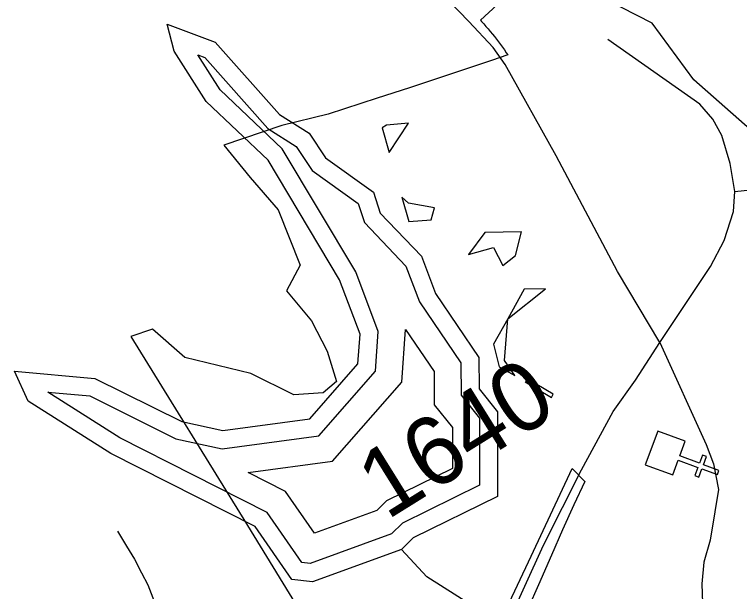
# Model space of a CAD drawing. Extents: x 2001466 to 31450019, y -30647475 to 847247.
# Drawn here: x 31437067 to 31439706, y -30623518 to -30621416 of the extents above; entities that cross this region are included whole.
import ezdxf

# ---------------------------------------------------------------- set-up
doc = ezdxf.new("R2010")
doc.units = 0
for name, color, linetype in [('Exist Boundary Political City Limit New Hole', 7, 'Continuous'), ('Exist Cultural Church CELL', 7, 'Continuous'), ('Exist Hydrographic Buffer Line', 7, 'Continuous'), ('Exist Hydrographic Creek Single Shore', 7, 'Continuous'), ('Exist Hydrographic Lake Shore', 7, 'Continuous'), ('Exist Road Non-System Type 51', 7, 'Continuous'), ('Exist Road Secondary Type 51 Attributed', 7, 'Continuous'), ('Exist Road Secondary Type 51 Number Label', 7, 'Continuous'), ('Map Preparation Boundary City Limit Buffer Line', 7, 'Continuous')]:
    doc.layers.add(name, color=color, linetype=linetype)

msp = doc.modelspace()

# ---------------------------------------------------------------- linework, layer by layer
at = {"layer": 'Exist Boundary Political City Limit New Hole'}
for points in [[(31438430.3, -30621919.4), (31438500.8, -30621812.3), (31438421, -30621819.8), (31438404.8, -30621829.8), (31438430.3, -30621919.4)], [(31438501.4, -30622104), (31438476.8, -30622082.1), (31438502.1, -30622170.6), (31438583, -30622164.5), (31438596, -30622120.6), (31438501.4, -30622104)], [(31438889.9, -30622293.8), (31438912, -30622208.7), (31438779, -30622211), (31438719.3, -30622291.1), (31438810.8, -30622265.3), (31438844.6, -30622330.2), (31438889.9, -30622293.8)], [(31438862.9, -30622525.3), (31438999.4, -30622415.7), (31438921.6, -30622416.9), (31438862.9, -30622525.3)], [(31438862.9, -30622525.3), (31438810.3, -30622617), (31438831, -30622699.5), (31438887.9, -30622731.8)], [(31438887.9, -30622731.8), (31438851, -30622676.8), (31438862.9, -30622525.3)], [(31438925.9, -30622754), (31439021.5, -30622811.4), (31439027.8, -30622799.3), (31438968.4, -30622764.3), (31438966.3, -30622763.8), (31438925.9, -30622754)]]:
    msp.add_lwpolyline(points, dxfattribs=at)
at = {"layer": 'Exist Cultural Church CELL'}
msp.add_lwpolyline([(31439408.4, -30622934.2), (31439363, -30623056.7), (31439462.8, -30623093.7), (31439483, -30623039.7), (31439554.4, -30623066.1), (31439543.3, -30623096.1), (31439558.2, -30623101.7), (31439569.4, -30623071.7), (31439625.7, -30623092.5), (31439631.3, -30623077.5), (31439574.9, -30623056.6), (31439586, -30623026.6), (31439571, -30623021.1), (31439559.9, -30623051.1), (31439488.5, -30623024.6), (31439508.2, -30622971.2), (31439408.4, -30622934.2)], dxfattribs=at)
at = {"layer": 'Exist Hydrographic Buffer Line'}
for points in [[(31437187.3, -30622792.6), (31437340.4, -30622806.1), (31437653.6, -30622961.6), (31437822.8, -30622998.4), (31438174.6, -30622950.7), (31438380.3, -30622716), (31438391, -30622571.4), (31438308.8, -30622354), (31438041.2, -30621906.3), (31437815.5, -30621691), (31437733.8, -30621563.3)], [(31437733.8, -30621563.3), (31437759, -30621572.8), (31437988.6, -30621831.7), (31438092.4, -30621896.9), (31438150.3, -30621985), (31438317.9, -30622104.6), (31438340.6, -30622174.2), (31438491.7, -30622332.6), (31438540.8, -30622462.9), (31438692, -30622685.8), (31438693, -30622803.4), (31438758.9, -30622886.6), (31438759.7, -30623131.3), (31438478.9, -30623269.1), (31438439.4, -30623308.4)], [(31437916.8, -30623085), (31438224.3, -30623043.3), (31438476.1, -30622756.1), (31438490.3, -30622563.8)], [(31438490.3, -30622563.8), (31438593.8, -30622716.4), (31438594.9, -30622838), (31438660.6, -30622921), (31438661.1, -30623070), (31438420.9, -30623187.9), (31438385.3, -30623223.3)], [(31438439.4, -30623308.4), (31438143.3, -30623416.2), (31438113.2, -30623413), (31437987, -30623231), (31437449.8, -30622958.2), (31437187.3, -30622792.6)], [(31438385.3, -30623223.3), (31438158.7, -30623305.9), (31438053.7, -30623154.5), (31437916.8, -30623085)]]:
    msp.add_lwpolyline(points, dxfattribs=at)
at = {"layer": 'Exist Hydrographic Creek Single Shore'}
for points in [[(31439888.4, -30621961.3), (31439539.5, -30621654.5), (31439388.3, -30621448), (31438996.5, -30621246.3), (31438888.4, -30621129.3), (31438779.3, -30620940), (31438746.5, -30620821.2), (31438753.5, -30620214.4), (31438794.3, -30620077.4)], [(31440512.4, -30625135.9), (31440412.4, -30625078), (31440328.5, -30624787.5), (31440294.5, -30624770.5), (31440277.4, -30624694.7), (31440194.4, -30624627.4), (31439927.4, -30624579.3), (31439877.4, -30624443.7), (31439760.5, -30624369.1), (31439693.5, -30624262.8), (31439260.4, -30624053.8), (31438998.6, -30623756.5), (31438963.5, -30623729.3), (31438939.7, -30623703.8), (31438905.2, -30623679.5), (31438856.5, -30623647.7), (31438567.5, -30623465.4), (31438475.4, -30623365.1)]]:
    msp.add_lwpolyline(points, dxfattribs=at)
at = {"layer": 'Exist Hydrographic Lake Shore'}
for points in [[(31437066.5, -30622716.1), (31437358.5, -30622741.8), (31437675.5, -30622899.2), (31437825.4, -30622931.8), (31438141.4, -30622889), (31438316.5, -30622689.2), (31438324.5, -30622581.1), (31438249.5, -30622382.6), (31437989.5, -30621947.6), (31437764.5, -30621733), (31437647.4, -30621550.1), (31437622.4, -30621451.2)], [(31437622.4, -30621451.2), (31437797.3, -30621517.1), (31438031.5, -30621781.1), (31438139.4, -30621848.9), (31438198.4, -30621938.8), (31438373.5, -30622063.7), (31438398.3, -30622139.7), (31438548.4, -30622297), (31438599.5, -30622432.5), (31438757.4, -30622665.4), (31438758.4, -30622780.3), (31438824.4, -30622863.6), (31438825.5, -30623172.1), (31438517.5, -30623323.3), (31438475.4, -30623365.1)], [(31438475.4, -30623365.1), (31438151.5, -30623483.1), (31438076.4, -30623475.1), (31437942.5, -30623282), (31437417.4, -30623015.3), (31437116.4, -30622825.5), (31437066.5, -30622716.1)]]:
    msp.add_lwpolyline(points, dxfattribs=at)
at = {"layer": 'Exist Road Non-System Type 51'}
for points in [[(31439688.5, -30622061.4), (31439672, -30621959.5), (31439641.7, -30621857.7), (31439608.7, -30621797.2), (31439561.6, -30621742.9), (31439226.7, -30621507.6)], [(31439688.5, -30622061.4), (31439757.3, -30622053.5), (31439793.1, -30622044.7), (31439815, -30622030.2), (31439831.5, -30622009.1), (31439850.7, -30621981.6), (31439875.5, -30621943)], [(31439445.5, -30622567.4), (31439599.9, -30622334.2), (31439650, -30622240.2), (31439684, -30622134.4), (31439688.5, -30622061.4)], [(31439416.4, -30622611.4), (31439584.1, -30622982.3), (31439611.9, -30623053.3), (31439629.2, -30623146.2), (31439616.4, -30623227.8), (31439598.9, -30623330.8), (31439576.1, -30623411.2), (31439569, -30623490.5), (31439571.2, -30623561.4), (31439585, -30623627.7), (31439592.4, -30623666.3), (31439659.5, -30623814)], [(31437441.9, -30623298.9), (31437474.8, -30623353.6), (31437503.9, -30623400.2), (31437528.8, -30623450.7), (31437551.6, -30623493.7), (31437570, -30623541), (31437583.2, -30623580.4), (31437591, -30623651.4), (31437601.6, -30623685.6), (31437625.2, -30623717.1), (31437651.5, -30623732.9), (31437696.1, -30623769.7), (31437732.9, -30623819.7), (31437759.2, -30623869.6), (31437785, -30623933.9), (31437840.6, -30623993.2), (31437893.2, -30624035.3), (31437916.8, -30624045.8), (31437948.4, -30624064.2), (31437966.8, -30624077.3), (31438000.9, -30624093.1)]]:
    msp.add_lwpolyline(points, dxfattribs=at)
at = {"layer": 'Exist Road Secondary Type 51 Attributed'}
for points in [[(31439416.4, -30622611.4), (31439261.9, -30622352.1), (31439039, -30621931.8), (31438852.3, -30621598.4), (31438809.7, -30621537.2), (31438721.2, -30621442.2), (31438611.7, -30621327.8), (31438460.4, -30621189.3), (31438325.3, -30621047.6), (31438176.8, -30620875.3), (31438011.8, -30620696.5), (31437815.5, -30620488.8), (31437647.7, -30620306), (31437562.8, -30620220.1)], [(31439416.4, -30622611.4), (31439445.5, -30622567.4)], [(31438951.3, -30624488.5), (31438831.4, -30624387.8), (31438778.3, -30624315.3), (31438749.3, -30624242.8), (31438739.7, -30624085), (31438748.5, -30623917.5), (31438772.7, -30623816.1), (31438856.5, -30623647.7), (31438992.3, -30623349), (31439130.8, -30623075.2), (31439245.8, -30622862.6), (31439327.9, -30622748.3), (31439416.4, -30622611.4)]]:
    msp.add_lwpolyline(points, dxfattribs=at)
at = {"layer": 'Map Preparation Boundary City Limit Buffer Line'}
for points in [[(31438970.4, -30621193.5), (31439007.8, -30621210.6), (31438992.1, -30621225.1), (31438990.5, -30621226.6), (31438763.3, -30621437.1), (31438767, -30621441.3), (31438775, -30621450.3), (31438783, -30621459.6), (31438790.9, -30621468.8), (31438798.6, -30621478.2), (31438806.3, -30621487.6), (31438813.9, -30621497.1), (31438821.3, -30621506.6), (31438828.6, -30621516.3)], [(31438828.6, -30621516.3), (31438835.9, -30621526), (31438843, -30621535.8), (31438850.1, -30621545.7), (31438857.1, -30621555.7), (31438862.1, -30621563.1), (31438803.6, -30621583.9), (31438614.4, -30621647.6), (31438504.3, -30621683.3), (31438386.6, -30621721.5), (31438208.8, -30621779.1), (31438040, -30621820.4), (31437828.3, -30621892.6), (31437924.5, -30622009.8), (31438025.9, -30622128.1), (31438106.4, -30622329.6), (31438057, -30622423.2), (31438147.3, -30622532.6), (31438204.3, -30622643.1), (31438239.1, -30622753.8), (31438189.8, -30622794.7), (31438084, -30622802.3), (31437927.4, -30622724.5), (31437686.1, -30622665.5), (31437569.1, -30622563), (31437490.5, -30622589), (31437910.8, -30623271.9), (31437914.5, -30623278), (31438136, -30623638.1)], [(31438430.3, -30621919.4), (31438500.8, -30621812.3), (31438421, -30621819.8), (31438404.8, -30621829.8), (31438430.3, -30621919.4)], [(31438501.4, -30622104), (31438476.8, -30622082.1), (31438502.1, -30622170.6), (31438583, -30622164.5), (31438596, -30622120.6), (31438501.4, -30622104)], [(31438889.9, -30622293.8), (31438912, -30622208.7), (31438779, -30622211), (31438719.3, -30622291.1), (31438810.8, -30622265.3), (31438844.6, -30622330.2), (31438889.9, -30622293.8)], [(31438862.9, -30622525.3), (31438999.4, -30622415.7), (31438921.6, -30622416.9), (31438862.9, -30622525.3)], [(31438862.9, -30622525.3), (31438810.3, -30622617), (31438831, -30622699.5), (31438887.9, -30622731.8)], [(31438887.9, -30622731.8), (31438851, -30622676.8), (31438862.9, -30622525.3)], [(31438925.9, -30622754), (31439021.5, -30622811.4), (31439027.8, -30622799.3), (31438968.4, -30622764.3), (31438966.3, -30622763.8), (31438925.9, -30622754)], [(31438857.8, -30623580.8), (31438947.5, -30623389.1), (31439096.9, -30623069.7), (31439142.5, -30623117.5), (31439103.3, -30623202.9), (31439062.1, -30623294), (31439021.4, -30623385.4), (31438974, -30623493.5), (31438936.8, -30623578.6)]]:
    msp.add_lwpolyline(points, dxfattribs=at)

# ---------------------------------------------------------------- texts
at = {"layer": 'Exist Road Secondary Type 51 Number Label'}
msp.add_text('1640', height=250, rotation=31.918, dxfattribs=at).set_placement((31438421.7, -30623260.3))

doc.saveas('drawing.dxf')
